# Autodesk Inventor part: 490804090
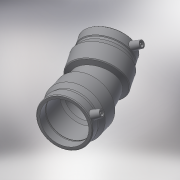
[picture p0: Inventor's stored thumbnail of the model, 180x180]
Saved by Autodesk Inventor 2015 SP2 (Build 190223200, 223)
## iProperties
Created: 2017-06
Part Number: 490804090
Material: Generic
Description: PLASSON 22.5° ELBOW 90
Document SubType Name: Modeling
Designer: KIM
Mass: 55.0731 g
Surface Area: 148.067 cm^2
Volume: 55.0731 cm^3
Density: 1 g/cm^3
Appearance: Default
Author: KIM
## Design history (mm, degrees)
derived "490804.ipt"
feature "Solid1::490804.ipt"
tag "TaggingFeature1"
body "Solid1"
other parameters: "d14" = 17.6296, "d19" = 3.52592, "d20" = 168 deg, "d22" = 103.96, "d23" = 113, "d24" = 100.8412, "d29" = 71, "d35" = 15, "d39" = 5 deg, "d45" = 4, "d46" = 14, "d47" = 0, "d67" = 45 deg, "d71" = 157.5 deg, "d75" = 5.65, "d82" = 45 deg, "d83" = 72, "d84" = 101.7, "d94" = 157.5 deg, "d95" = 50.4206, "d98" = 214, "d99" = 64.2, "d105" = 20.88, "d106" = 5.22, "L_" = 214, "L_1" = 72, "D_" = 113, "A_" = 71, "d_2" = 12
